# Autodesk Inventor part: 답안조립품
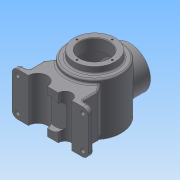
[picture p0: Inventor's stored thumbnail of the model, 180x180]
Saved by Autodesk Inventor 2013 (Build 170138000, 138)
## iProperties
Created: 2018-08
Part Number: 답안조립품
Material: 일반
Document SubType Name: Modeling
Designer: user
Density: 1 g/cm^3
Author: user
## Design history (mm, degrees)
sketch "스케치1"
  geometry: L1 (70, -40)-(-70, -40); L2 (-70, -40)-(-70, 40); L3 (-70, 40)-(70, 40); L4 (70, 40)-(70, -40); L5 (70, -40)-(-70, 40); L6 (-70, -40)-(70, 40); 1 further point
  constraints: 12 end point, 2 midpoint, 2 parallel, 1 horizontal, 1 perpendicular
  dimensions: "d0" = 140 distance of L2.end L3.end; "d1" = 80 distance of L1.end L2.end
extrude "돌출1" new body sketch "스케치1" distance "d2" = 10; taper "d3" = 0 deg
sketch "스케치4"
  geometry: L1 (82, 60)-(120, 60); L2 (120, 60)-(120, 48); L3 (120, 48)-(132, 48); L4 (132, 48)-(132, -48.671); L5 (82, 60)-(82, -60); L6 (0, 40)-(0, -40) reference; L7 (0, 40)-(10, 40) reference; A1 r 116 centre (82, 56) between (82, -60) and (132, -48.671); 1 further point
  constraints: 10 end point, 3 parallel, 2 point on circle, 1 centre point, 1 horizontal, 1 perpendicular, 1 point on line
  dimensions: "d6" = 116 radius of A1; "d7" = 108 distance from line of L5.end L3; "d9" = 76 diameter of L2 L5; "d10" = 82 distance from line of L6 L5.end; "d11" = 100 diameter of L4 L5; "d12" = 8 distance between parallel lines of L7 L3; "d13" = 12 distance of L1.end L2.end
revolve "회전1" sketch "스케치4" stored, may be unused: angle "d14" = 90 deg
sketch "스케치5"
  geometry: L1 (10, -40)-(0, -40) reference; L2 (0, -40)-(0, 40) reference; L3 (0, 40)-(10, 40) reference; L4 (10, 40)-(10, -40) reference; L5 (44, 48)-(44, 60) reference; L6 (44, 60)-(120, 60) reference; L7 (120, 60)-(120, 48) reference; L8 (120, 48)-(132, 48) reference; L9 (132, 48)-(132, -48.671) reference; L10 (32, -48.671)-(32, 48) reference; L11 (32, 48)-(44, 48) reference; L12 (122, 38)-(109, 38); L13 (109, 38)-(109, 60); L14 (39.614, 40.386)-(39.614, 40); L15 (82, 60)-(82, -50); L16 (122, 38)-(122, -42.163); L17 (109, 60)-(82, 60); A1 r 116 centre (82, 56) between (32, -48.671) and (82, -60) reference; A2 r 116 centre (82, 56) between (82, -60) and (132, -48.671) reference; A3 r 106 centre (82, 56) between (82, -50) and (122, -42.163); 1 further point
  constraints: 12 end point, 3 point on line, 2 parallel, 2 point on circle, 1 centre point, 1 collinear, 1 midpoint
  dimensions: "d18" = 10 radial gap between concentric circles of A1 A3; "d19" = 54 diameter of L13 L15; "d20" = 80 diameter of L16 L15; "d21" = 82 distance from line of L15.start L2; "d22" = 22 distance of L12.end L13.end
revolve "회전2" sketch "스케치5" stored, may be unused: angle "d23" = 90 deg
sketch "스케치6"
  geometry: L1 (-50, 40)-(50, 40); L2 (50, 40)-(50, -40); L3 (50, -40)-(-50, -40); L4 (-50, -40)-(-50, 40); L5 (-50, 40)-(50, -40); L6 (50, 40)-(-50, -40); 1 further point
  constraints: 12 end point, 2 midpoint, 2 parallel, 1 horizontal, 1 perpendicular
  dimensions: "d24" = 100 distance of L2.end L3.end; "d25" = 80 distance of L1.end L2.end
node "작업 평면2"
sketch "스케치7"
  geometry: C1 r 38 at (0, 0); 1 further point
  constraints: 1 centre point, 1 coincident
  dimensions: "d27" = 76 diameter of C1
extrude "돌출2" join sketch "스케치7" stored distance "d28" = 10; taper "d29" = 0 deg
sketch "스케치8" dims "d30" = 65
  geometry: 3 further points
  constraints: 1 coincident, 1 vertical alignment, 2 other
hole "구멍1" sketch "스케치8" at (0, 32.5) diameter "d31" = 3.242; stored, may be unused: countersink angle "d35" = 90 deg, drill point angle "d37" = 118 deg; dims "d32" = 8, "d33" = 4, "d34" = 2, "d36" = 10
sketch "스케치9"
  geometry: C1 r 27 at (0, 0); 1 further point
  constraints: 1 centre point, 1 coincident
  dimensions: "d41" = 54 diameter of C1
extrude "돌출3" cut sketch "스케치9" stored distance "d42" = 10; taper "d43" = 0 deg
sketch "스케치10" dims "d44" = 65
  geometry: C1 r 50 at (0, 0) reference; C2 r 38 at (0, 0) reference; 3 further points
  constraints: 1 coincident, 1 vertical alignment, 2 other
hole "구멍2" sketch "스케치10" at (0, 32.5) diameter "d45" = 3.242; stored, may be unused: countersink angle "d49" = 90 deg, drill point angle "d51" = 118 deg; dims "d46" = 8, "d47" = 4, "d48" = 2, "d50" = 10
node "작업 평면3"
node "작업 평면4"
sketch "스케치15" dims "d59" = 65
  geometry: C1 r 50 at (0, 82) reference; 3 further points
  constraints: 1 coincident, 1 vertical alignment, 2 other
  node "투영된 루프5"
extrude "돌출4" join sketch "스케치6" distance "d61" = 28.563; taper "d62" = 0 deg
sketch "스케치19"
  geometry: L1 (-70, 10)-(-50, 10) reference; L2 (-50, 38.563)-(-40.304, 52.41); L3 (-70, 0)-(-70, 10) reference; L4 (-24.763, 38.563)-(-50, 38.563); L5 (-50, 38.563)-(-24.763, 38.563); C1 r 38 at (0, 82) reference; A1 r 50 centre (0, 82) between (-40.304, 52.41) and (-24.763, 38.563); A2 r 50 centre (0, 82) between (-40.304, 52.41) and (-24.763, 38.563); 2 further points
  constraints: 6 end point, 4 point on circle, 2 centre point, 1 collinear, 3 other
  dimensions: "d63" = 35 deg angle of L3 L2
extrude "돌출5" join sketch "스케치19" stored distance "d64" = 80; taper "d65" = 0 deg
sketch "스케치20"
  geometry: L1 (-70, 40)-(70, 40) reference; L2 (70, 40)-(70, -40) reference; L3 (70, -40)-(-70, -40) reference; L4 (-70, -40)-(-70, 40) reference; L5 (70, 0)-(0, 0); C1 r 27 at (0, 0) reference; C2 r 4 at (60, 30); C3 r 4 at (60, -30); 1 further point
  constraints: 2 centre point, 2 end point, 1 midpoint, 1 perpendicular, 1 symmetric about line, 1 other
  dimensions: "d67" = 8 diameter of C2; "d68" = 10 distance from line of C2.centre L1; "d69" = 10 distance from line of C2.centre L2
extrude "돌출6" cut sketch "스케치20" stored distance "d70" = 8 (= d67); taper "d71" = 0 deg
sketch "스케치27"
  geometry: L1 (140, 0)-(0, 0) reference; A1 r 12.5 centre (42.5, 0) between (55, 0) and (30, 0); A2 r 17.5 centre (92.5, 0) between (110, 0) and (75, 0); 1 further point
  constraints: 4 point on circle, 4 point on line, 2 centre point
  dimensions: "d81" = 12.5 radius of A1; "d82" = 17.5 radius of A2; "d83" = 27.5 distance of point (70, 0) A1.centre; "d84" = 22.5 distance of A2.centre point (70, 0)
extrude "돌출7" cut sketch "스케치27" stored distance "d85" = 8 (= d67); taper "d86" = 0 deg
fillet "모깎기1" dims "d87" = 3
chamfer "모따기1" distance "d88" = 1; stored, may be unused: second distance "d89" = 2, angle "d90" = 45 deg
fillet "모깎기2" dims "d91" = 10
fillet "모깎기3" dims "d92" = 3
fillet "모깎기4" dims "d93" = 3
fillet "모깎기5" dims "d94" = 3
fillet "모깎기6" dims "d95" = 3
feature "엠보싱1" dims "d96" = 0.5, "d97" = 0
fillet "모깎기7" dims "d98" = 3
chamfer "모따기2" distance "d99" = 1; stored, may be unused: second distance "d100" = 2, angle "d101" = 45 deg
node "솔리드1"
pattern_circular "원형 패턴1" dims angle "d39" = 360 deg
pattern_circular "원형 패턴2" dims angle "d53" = 360 deg
mirror "대칭1"
mirror "대칭2"
node "투영된 루프2"
node "투영된 루프7"
node "투영된 루프8"
node "절단 모서리 투영1"
other parameters: "d26" = 147, "d57" = 0
